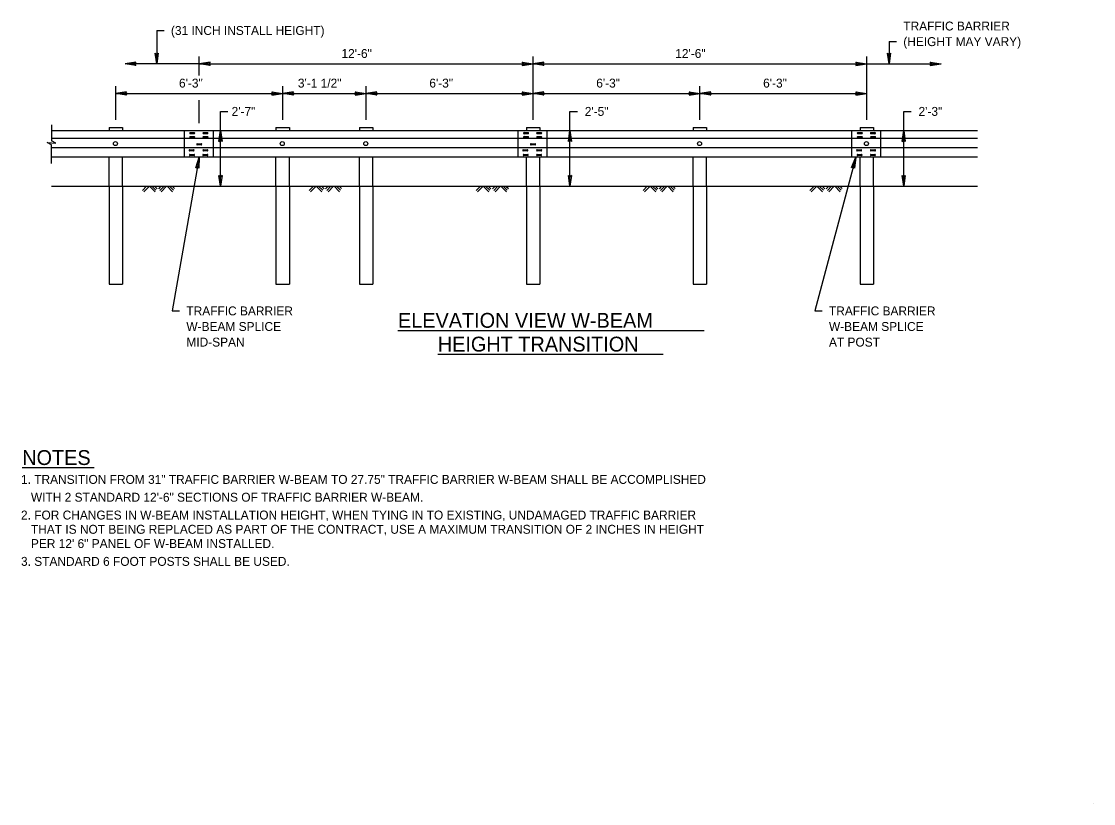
# Model space of a CAD drawing. Extents: x 12.39 to 19.62, y 5.98 to 15.84.
# Drawn here: x 12.4 to 19.62, y 5.98 to 11.25 of the extents above; entities that cross this region are included whole.
import ezdxf

# ---------------------------------------------------------------- set-up
doc = ezdxf.new("R2010")
doc.units = 0
for name, color, linetype in [('DETL-DIMS', 7, 'Continuous'), ('DETL-LINE', 7, 'Continuous'), ('DETL-NOTE', 7, 'Continuous'), ('DETL-PATT', 7, 'Continuous'), ('DETL-TITL', 7, 'Continuous'), ('TTLB-TEXT', 7, 'Continuous')]:
    doc.layers.add(name, color=color, linetype=linetype)

msp = doc.modelspace()

# ---------------------------------------------------------------- linework, layer by layer
at = {"layer": 'DETL-DIMS'}
for p, q in [((13.311, 11.1902), (13.311, 10.9652)), ((13.311, 11.1902), (13.361, 11.1902)), ((18.2435, 11.1152), (18.2435, 10.9652)), ((18.2435, 11.1152), (18.2935, 11.1152)), ((13.3004, 11.0381), (13.311, 10.9652)), ((13.3004, 11.0381), (13.311, 11.029)), ((13.3216, 11.0381), (13.311, 10.9652)), ((13.3216, 11.0381), (13.311, 11.029)), ((13.5972, 10.8864), (13.5972, 11.0152)), ((15.8453, 10.5879), (15.8453, 11.0152)), ((18.0935, 10.5879), (18.0935, 11.0152)), ((18.2329, 11.0381), (18.2435, 10.9652)), ((18.2329, 11.0381), (18.2435, 11.029)), ((18.2541, 11.0381), (18.2435, 10.9652)), ((18.2541, 11.0381), (18.2435, 11.029)), ((13.1701, 10.9758), (13.0972, 10.9652)), ((13.1701, 10.9546), (13.0972, 10.9652)), ((13.5972, 10.9652), (13.0972, 10.9652)), ((13.1701, 10.9758), (13.161, 10.9652)), ((13.1701, 10.9546), (13.161, 10.9652)), ((13.6701, 10.9758), (13.5972, 10.9652)), ((13.5972, 10.9652), (15.8453, 10.9652)), ((13.6701, 10.9546), (13.5972, 10.9652)), ((13.6701, 10.9758), (13.661, 10.9652)), ((13.6701, 10.9546), (13.661, 10.9652)), ((15.7724, 10.9758), (15.8453, 10.9652)), ((15.7724, 10.9758), (15.7815, 10.9652)), ((15.7724, 10.9546), (15.8453, 10.9652)), ((15.7724, 10.9546), (15.7815, 10.9652)), ((15.9182, 10.9758), (15.8453, 10.9652)), ((15.8453, 10.9652), (18.0935, 10.9652)), ((15.9182, 10.9546), (15.8453, 10.9652)), ((15.9182, 10.9758), (15.9091, 10.9652)), ((15.9182, 10.9546), (15.9091, 10.9652)), ((18.0206, 10.9758), (18.0935, 10.9652)), ((18.0206, 10.9758), (18.0297, 10.9652)), ((18.0206, 10.9546), (18.0935, 10.9652)), ((18.0206, 10.9546), (18.0297, 10.9652)), ((18.0935, 10.9652), (18.5935, 10.9652)), ((18.5206, 10.9758), (18.5935, 10.9652)), ((18.5206, 10.9758), (18.5297, 10.9652)), ((18.5206, 10.9546), (18.5935, 10.9652)), ((18.5206, 10.9546), (18.5297, 10.9652)), ((13.0351, 10.5879), (13.0351, 10.8159)), ((13.108, 10.7765), (13.0351, 10.7659)), ((13.0351, 10.7659), (14.1592, 10.7659)), ((13.108, 10.7553), (13.0351, 10.7659)), ((13.108, 10.7765), (13.0989, 10.7659)), ((13.108, 10.7553), (13.0989, 10.7659)), ((14.0863, 10.7765), (14.1592, 10.7659)), ((14.0863, 10.7765), (14.0954, 10.7659)), ((14.0863, 10.7553), (14.1592, 10.7659)), ((14.0863, 10.7553), (14.0954, 10.7659)), ((14.1592, 10.5879), (14.1592, 10.8159)), ((14.2321, 10.7765), (14.1592, 10.7659)), ((14.1592, 10.7659), (14.7212, 10.7659)), ((14.2321, 10.7553), (14.1592, 10.7659)), ((14.2321, 10.7765), (14.223, 10.7659)), ((14.2321, 10.7553), (14.223, 10.7659)), ((14.6483, 10.7765), (14.7212, 10.7659)), ((14.6483, 10.7765), (14.6574, 10.7659)), ((14.6483, 10.7553), (14.7212, 10.7659)), ((14.6483, 10.7553), (14.6574, 10.7659)), ((14.7212, 10.5879), (14.7212, 10.8159)), ((14.7941, 10.7765), (14.7212, 10.7659)), ((14.7212, 10.7659), (15.8453, 10.7659)), ((14.7941, 10.7553), (14.7212, 10.7659)), ((14.7941, 10.7765), (14.785, 10.7659)), ((14.7941, 10.7553), (14.785, 10.7659)), ((15.7724, 10.7765), (15.8453, 10.7659)), ((15.7724, 10.7765), (15.7815, 10.7659)), ((15.7724, 10.7553), (15.8453, 10.7659)), ((15.7724, 10.7553), (15.7815, 10.7659)), ((15.9182, 10.7765), (15.8453, 10.7659)), ((15.8453, 10.7659), (16.9694, 10.7659)), ((15.9182, 10.7553), (15.8453, 10.7659)), ((15.9182, 10.7765), (15.9091, 10.7659)), ((15.9182, 10.7553), (15.9091, 10.7659)), ((16.8965, 10.7765), (16.9694, 10.7659)), ((16.8965, 10.7765), (16.9056, 10.7659)), ((16.8965, 10.7553), (16.9694, 10.7659)), ((16.8965, 10.7553), (16.9056, 10.7659)), ((16.9694, 10.5879), (16.9694, 10.8159)), ((17.0423, 10.7765), (16.9694, 10.7659)), ((16.9694, 10.7659), (18.0935, 10.7659)), ((17.0423, 10.7553), (16.9694, 10.7659)), ((17.0423, 10.7765), (17.0332, 10.7659)), ((17.0423, 10.7553), (17.0332, 10.7659)), ((18.0206, 10.7765), (18.0935, 10.7659)), ((18.0206, 10.7765), (18.0297, 10.7659)), ((18.0206, 10.7553), (18.0935, 10.7659)), ((18.0206, 10.7553), (18.0297, 10.7659)), ((13.5972, 10.5659), (13.5972, 10.7216)), ((13.7403, 10.5159), (13.7403, 10.6454)), ((13.7403, 10.6454), (13.7903, 10.6454)), ((16.0939, 10.5159), (16.0939, 10.6454)), ((16.0939, 10.6454), (16.1439, 10.6454)), ((18.3421, 10.5159), (18.3421, 10.6454)), ((18.3421, 10.6454), (18.3921, 10.6454)), ((13.7297, 10.443), (13.7403, 10.5159)), ((13.7403, 10.1413), (13.7403, 10.5159)), ((13.7509, 10.443), (13.7403, 10.5159)), ((16.0833, 10.443), (16.0939, 10.5159)), ((16.0939, 10.1413), (16.0939, 10.5159)), ((16.1045, 10.443), (16.0939, 10.5159)), ((18.3315, 10.443), (18.3421, 10.5159)), ((18.3421, 10.1413), (18.3421, 10.5159)), ((18.3527, 10.443), (18.3421, 10.5159)), ((13.7297, 10.443), (13.7403, 10.4521)), ((13.7509, 10.443), (13.7403, 10.4521)), ((16.0833, 10.443), (16.0939, 10.4521)), ((16.1045, 10.443), (16.0939, 10.4521)), ((18.3315, 10.443), (18.3421, 10.4521)), ((18.3527, 10.443), (18.3421, 10.4521)), ((13.5972, 10.3361), (13.4148, 9.3018)), ((13.5741, 10.2661), (13.5972, 10.3361)), ((13.5949, 10.2625), (13.5972, 10.3361)), ((18.02, 10.3361), (17.7429, 9.3018)), ((17.9909, 10.2684), (18.02, 10.3361)), ((18.0114, 10.2629), (18.02, 10.3361)), ((13.5741, 10.2661), (13.5861, 10.2733)), ((13.5949, 10.2625), (13.5861, 10.2733)), ((17.9909, 10.2684), (18.0035, 10.2745)), ((18.0114, 10.2629), (18.0035, 10.2745)), ((13.7297, 10.2142), (13.7403, 10.1413)), ((13.7297, 10.2142), (13.7403, 10.2051)), ((13.7509, 10.2142), (13.7403, 10.1413)), ((13.7509, 10.2142), (13.7403, 10.2051)), ((16.0833, 10.2142), (16.0939, 10.1413)), ((16.0833, 10.2142), (16.0939, 10.2051)), ((16.1045, 10.2142), (16.0939, 10.1413)), ((16.1045, 10.2142), (16.0939, 10.2051)), ((18.3315, 10.2142), (18.3421, 10.1413)), ((18.3315, 10.2142), (18.3421, 10.2051)), ((18.3527, 10.2142), (18.3421, 10.1413)), ((18.3527, 10.2142), (18.3421, 10.2051)), ((13.4148, 9.3018), (13.4648, 9.3018)), ((17.7429, 9.3018), (17.7929, 9.3018))]:
    msp.add_line(p, q, dxfattribs=at)
for points in [[(13.3216, 11.0381), (13.311, 10.9652), (13.3004, 11.0381), (13.311, 11.029)], [(18.2541, 11.0381), (18.2435, 10.9652), (18.2329, 11.0381), (18.2435, 11.029)], [(13.1701, 10.9546), (13.0972, 10.9652), (13.1701, 10.9758), (13.161, 10.9652)], [(13.6701, 10.9546), (13.5972, 10.9652), (13.6701, 10.9758), (13.661, 10.9652)], [(15.7724, 10.9758), (15.8453, 10.9652), (15.7724, 10.9546), (15.7815, 10.9652)], [(15.9182, 10.9546), (15.8453, 10.9652), (15.9182, 10.9758), (15.9091, 10.9652)], [(18.0206, 10.9758), (18.0935, 10.9652), (18.0206, 10.9546), (18.0297, 10.9652)], [(18.5206, 10.9758), (18.5935, 10.9652), (18.5206, 10.9546), (18.5297, 10.9652)], [(13.108, 10.7553), (13.0351, 10.7659), (13.108, 10.7765), (13.0989, 10.7659)], [(14.0863, 10.7765), (14.1592, 10.7659), (14.0863, 10.7553), (14.0954, 10.7659)], [(14.2321, 10.7553), (14.1592, 10.7659), (14.2321, 10.7765), (14.223, 10.7659)], [(14.6483, 10.7765), (14.7212, 10.7659), (14.6483, 10.7553), (14.6574, 10.7659)], [(14.7941, 10.7553), (14.7212, 10.7659), (14.7941, 10.7765), (14.785, 10.7659)], [(15.7724, 10.7765), (15.8453, 10.7659), (15.7724, 10.7553), (15.7815, 10.7659)], [(15.9182, 10.7553), (15.8453, 10.7659), (15.9182, 10.7765), (15.9091, 10.7659)], [(16.8965, 10.7765), (16.9694, 10.7659), (16.8965, 10.7553), (16.9056, 10.7659)], [(17.0423, 10.7553), (16.9694, 10.7659), (17.0423, 10.7765), (17.0332, 10.7659)], [(18.0206, 10.7765), (18.0935, 10.7659), (18.0206, 10.7553), (18.0297, 10.7659)], [(13.7297, 10.443), (13.7403, 10.5159), (13.7509, 10.443), (13.7403, 10.4521)], [(16.0833, 10.443), (16.0939, 10.5159), (16.1045, 10.443), (16.0939, 10.4521)], [(18.3315, 10.443), (18.3421, 10.5159), (18.3527, 10.443), (18.3421, 10.4521)], [(13.5741, 10.2661), (13.5972, 10.3361), (13.5949, 10.2625), (13.5861, 10.2733)], [(17.9909, 10.2684), (18.02, 10.3361), (18.0114, 10.2629), (18.0035, 10.2745)], [(13.7509, 10.2142), (13.7403, 10.1413), (13.7297, 10.2142), (13.7403, 10.2051)], [(16.1045, 10.2142), (16.0939, 10.1413), (16.0833, 10.2142), (16.0939, 10.2051)], [(18.3527, 10.2142), (18.3421, 10.1413), (18.3315, 10.2142), (18.3421, 10.2051)]]:
    msp.add_lwpolyline(points, close=True, dxfattribs=at)
at = {"layer": 'DETL-LINE'}
for p, q in [((12.6022, 10.5543), (12.6022, 10.4476)), ((12.6022, 10.5159), (13.8777, 10.5159)), ((12.9901, 10.5379), (12.9901, 10.5159)), ((12.9901, 10.5379), (13.0801, 10.5379)), ((13.0801, 10.5379), (13.0801, 10.5159)), ((13.4952, 10.5152), (13.4952, 10.3361)), ((13.5367, 10.5034), (13.5637, 10.5034)), ((13.5637, 10.4954), (13.5367, 10.4954)), ((13.5367, 10.4762), (13.5637, 10.4762)), ((13.6252, 10.5034), (13.6523, 10.5034)), ((13.6523, 10.4954), (13.6252, 10.4954)), ((13.6259, 10.4756), (13.6528, 10.4756)), ((13.6903, 10.5152), (13.6903, 10.3361)), ((13.8777, 10.5159), (16.1259, 10.5159)), ((14.1142, 10.5379), (14.1142, 10.5159)), ((14.1142, 10.5379), (14.2042, 10.5379)), ((14.2042, 10.5379), (14.2042, 10.5159)), ((14.6763, 10.5379), (14.6763, 10.5159)), ((14.6763, 10.5379), (14.7662, 10.5379)), ((14.7662, 10.5379), (14.7662, 10.5159)), ((15.7433, 10.5152), (15.7433, 10.3361)), ((15.7849, 10.5034), (15.8118, 10.5034)), ((15.8118, 10.4954), (15.7849, 10.4954)), ((15.7849, 10.4762), (15.8118, 10.4762)), ((15.8004, 10.5379), (15.8004, 10.5159)), ((15.8004, 10.5379), (15.8903, 10.5379)), ((15.8734, 10.5034), (15.9005, 10.5034)), ((15.9005, 10.4954), (15.8734, 10.4954)), ((15.8741, 10.4756), (15.9009, 10.4756)), ((15.8903, 10.5379), (15.8903, 10.5159)), ((15.9384, 10.5152), (15.9384, 10.3361)), ((16.1259, 10.5159), (18.3741, 10.5159)), ((16.9244, 10.5379), (16.9244, 10.5159)), ((16.9244, 10.5379), (17.0144, 10.5379)), ((17.0144, 10.5379), (17.0144, 10.5159)), ((17.9915, 10.5152), (17.9915, 10.3361)), ((18.033, 10.5034), (18.06, 10.5034)), ((18.06, 10.4954), (18.033, 10.4954)), ((18.033, 10.4762), (18.06, 10.4762)), ((18.0485, 10.5379), (18.1385, 10.5379)), ((18.0485, 10.5379), (18.0485, 10.5159)), ((18.1216, 10.5034), (18.1487, 10.5034)), ((18.1487, 10.4954), (18.1216, 10.4954)), ((18.1222, 10.4756), (18.1491, 10.4756)), ((18.1385, 10.5379), (18.1385, 10.5159)), ((18.1866, 10.5152), (18.1866, 10.3361)), ((18.3741, 10.5159), (18.8393, 10.5159)), ((12.6022, 10.4191), (12.572, 10.4355)), ((12.572, 10.4355), (12.631, 10.4308)), ((18.8393, 10.4635), (12.6022, 10.4635)), ((12.631, 10.4308), (12.6022, 10.4476)), ((12.6022, 10.294), (12.6022, 10.4191)), ((18.8393, 10.3992), (12.6022, 10.3992)), ((13.5637, 10.4682), (13.5367, 10.4682)), ((13.5837, 10.4277), (13.6106, 10.4277)), ((13.6106, 10.4197), (13.5837, 10.4197)), ((13.6528, 10.4676), (13.6259, 10.4676)), ((15.8118, 10.4682), (15.7849, 10.4682)), ((15.8318, 10.4277), (15.8588, 10.4277)), ((15.8588, 10.4197), (15.8318, 10.4197)), ((15.9009, 10.4676), (15.8741, 10.4676)), ((18.06, 10.4682), (18.033, 10.4682)), ((18.1491, 10.4676), (18.1222, 10.4676)), ((18.8393, 10.3361), (12.6022, 10.3361)), ((12.9901, 10.1413), (12.9901, 10.3361)), ((13.0801, 10.1413), (13.0801, 10.3361)), ((13.5318, 10.3873), (13.559, 10.3873)), ((13.559, 10.3793), (13.5318, 10.3793)), ((13.5349, 10.356), (13.5619, 10.356)), ((13.5619, 10.3481), (13.5349, 10.3481)), ((13.6245, 10.3557), (13.6516, 10.3557)), ((13.6516, 10.3476), (13.6245, 10.3476)), ((13.6252, 10.3874), (13.6521, 10.3874)), ((13.6521, 10.3794), (13.6252, 10.3794)), ((14.1142, 10.1413), (14.1142, 10.3361)), ((14.2042, 10.1413), (14.2042, 10.3361)), ((14.6763, 10.1413), (14.6763, 10.3361)), ((14.7662, 10.1413), (14.7662, 10.3361)), ((15.78, 10.3873), (15.8071, 10.3873)), ((15.8071, 10.3793), (15.78, 10.3793)), ((15.7831, 10.356), (15.8101, 10.356)), ((15.8101, 10.3481), (15.7831, 10.3481)), ((15.8004, 10.1413), (15.8004, 10.3361)), ((15.8727, 10.3557), (15.8998, 10.3557)), ((15.8998, 10.3476), (15.8727, 10.3476)), ((15.8734, 10.3874), (15.9003, 10.3874)), ((15.9003, 10.3794), (15.8734, 10.3794)), ((15.8903, 10.1413), (15.8903, 10.3361)), ((16.9244, 10.1413), (16.9244, 10.3361)), ((17.0144, 10.1413), (17.0144, 10.3361)), ((18.0282, 10.3873), (18.0553, 10.3873)), ((18.0553, 10.3793), (18.0282, 10.3793)), ((18.0312, 10.356), (18.0583, 10.356)), ((18.0583, 10.3481), (18.0312, 10.3481)), ((18.0485, 10.1413), (18.0485, 10.3361)), ((18.1209, 10.3557), (18.1479, 10.3557)), ((18.1479, 10.3476), (18.1209, 10.3476)), ((18.1216, 10.3874), (18.1484, 10.3874)), ((18.1484, 10.3794), (18.1216, 10.3794)), ((18.1385, 10.1413), (18.1385, 10.3361)), ((12.6022, 10.1413), (18.8393, 10.1413)), ((12.9901, 10.1413), (12.9901, 9.4818)), ((13.0801, 10.1413), (13.0801, 9.4818)), ((14.1142, 10.1413), (14.1142, 9.4818)), ((14.2042, 10.1413), (14.2042, 9.4818)), ((14.6763, 10.1413), (14.6763, 9.4818)), ((14.7662, 10.1413), (14.7662, 9.4818)), ((15.8004, 10.1413), (15.8004, 9.4818)), ((15.8903, 10.1413), (15.8903, 9.4818)), ((16.9244, 10.1413), (16.9244, 9.4818)), ((17.0144, 10.1413), (17.0144, 9.4818)), ((18.0485, 10.1413), (18.0485, 9.4818)), ((18.1385, 10.1413), (18.1385, 9.4818)), ((12.9901, 9.4818), (13.0802, 9.4818)), ((14.1142, 9.4818), (14.2042, 9.4818)), ((14.6763, 9.4818), (14.7663, 9.4818)), ((15.8004, 9.4818), (15.8904, 9.4818)), ((16.9244, 9.4818), (17.0145, 9.4818)), ((18.0485, 9.4818), (18.1385, 9.4818))]:
    msp.add_line(p, q, dxfattribs=at)
for centre in [(13.0327, 10.4286), (14.1568, 10.4286), (14.7188, 10.4286), (16.967, 10.4286), (18.0911, 10.4286)]:
    msp.add_circle(centre, 0.0135, dxfattribs=at)
for centre, start, end in [((13.5371, 10.4994), 96.52857, 263.47143), ((13.5371, 10.4722), 96.52857, 263.47143), ((13.5632, 10.4994), 276.52857, 83.47143), ((13.5632, 10.4722), 276.52857, 83.47143), ((13.6257, 10.4994), 96.52857, 263.47143), ((13.6262, 10.4716), 96.52857, 263.47143), ((13.6518, 10.4994), 276.52857, 83.47143), ((13.6523, 10.4716), 276.52857, 83.47143), ((15.7853, 10.4722), 96.52857, 263.47143), ((15.7853, 10.4994), 96.52857, 263.47143), ((15.8114, 10.4722), 276.52857, 83.47143), ((15.8114, 10.4994), 276.52857, 83.47143), ((15.8739, 10.4994), 96.52857, 263.47143), ((15.8744, 10.4716), 96.52857, 263.47143), ((15.9, 10.4994), 276.52857, 83.47143), ((15.9005, 10.4716), 276.52857, 83.47143), ((18.0335, 10.4994), 96.52857, 263.47143), ((18.0335, 10.4722), 96.52857, 263.47143), ((18.0596, 10.4994), 276.52857, 83.47143), ((18.0596, 10.4722), 276.52857, 83.47143), ((18.122, 10.4994), 96.52857, 263.47143), ((18.1226, 10.4716), 96.52857, 263.47143), ((18.1481, 10.4994), 276.52857, 83.47143), ((18.1487, 10.4716), 276.52857, 83.47143), ((13.5841, 10.4237), 96.52857, 263.47143), ((13.6102, 10.4237), 276.52857, 83.47143), ((15.8323, 10.4237), 96.52857, 263.47143), ((15.8584, 10.4237), 276.52857, 83.47143), ((13.5324, 10.3833), 96.52857, 263.47143), ((13.5354, 10.352), 96.52857, 263.47143), ((13.5585, 10.3833), 276.52857, 83.47143), ((13.5615, 10.352), 276.52857, 83.47143), ((13.6251, 10.3517), 96.52857, 263.47143), ((13.6256, 10.3834), 96.52857, 263.47143), ((13.6512, 10.3517), 276.52857, 83.47143), ((13.6517, 10.3834), 276.52857, 83.47143), ((15.7805, 10.3833), 96.52857, 263.47143), ((15.7835, 10.352), 96.52857, 263.47143), ((15.8066, 10.3833), 276.52857, 83.47143), ((15.8096, 10.352), 276.52857, 83.47143), ((15.8732, 10.3517), 96.52857, 263.47143), ((15.8738, 10.3834), 96.52857, 263.47143), ((15.8993, 10.3517), 276.52857, 83.47143), ((15.8999, 10.3834), 276.52857, 83.47143), ((18.0287, 10.3833), 96.52857, 263.47143), ((18.0317, 10.352), 96.52857, 263.47143), ((18.0548, 10.3833), 276.52857, 83.47143), ((18.0578, 10.352), 276.52857, 83.47143), ((18.1214, 10.3517), 96.52857, 263.47143), ((18.1219, 10.3834), 96.52857, 263.47143), ((18.1475, 10.3517), 276.52857, 83.47143), ((18.148, 10.3834), 276.52857, 83.47143)]:
    msp.add_arc(centre, 0.00406, start, end, dxfattribs=at)
at = {"layer": 'DETL-NOTE'}
msp.add_line((12.405, 8.2472), (12.8898, 8.2472), dxfattribs=at)
at = {"layer": 'DETL-PATT'}
for p, q in [((13.2423, 10.1413), (13.214, 10.1126)), ((13.2236, 10.1043), (13.259, 10.1403)), ((13.2637, 10.1404), (13.2998, 10.1048)), ((13.3059, 10.1146), (13.2794, 10.1404)), ((13.2978, 10.1406), (13.3136, 10.125)), ((13.324, 10.1228), (13.3418, 10.1408)), ((13.3599, 10.141), (13.3321, 10.1126)), ((13.3415, 10.1042), (13.3776, 10.141)), ((13.3809, 10.1411), (13.4179, 10.1048)), ((13.4238, 10.1146), (13.3967, 10.1411)), ((13.4149, 10.1413), (13.4316, 10.1251)), ((14.3664, 10.1413), (14.3381, 10.1126)), ((14.3477, 10.1043), (14.3831, 10.1403)), ((14.3878, 10.1404), (14.4239, 10.1048)), ((14.43, 10.1146), (14.4035, 10.1404)), ((14.4218, 10.1406), (14.4377, 10.125)), ((14.4481, 10.1228), (14.4659, 10.1408)), ((14.484, 10.141), (14.4562, 10.1126)), ((14.4656, 10.1042), (14.5017, 10.141)), ((14.505, 10.1411), (14.542, 10.1048)), ((14.5479, 10.1146), (14.5208, 10.1411)), ((14.539, 10.1413), (14.5557, 10.1251)), ((15.4905, 10.1413), (15.4622, 10.1126)), ((15.4718, 10.1043), (15.5071, 10.1403)), ((15.5118, 10.1404), (15.548, 10.1048)), ((15.5541, 10.1146), (15.5276, 10.1404)), ((15.5459, 10.1406), (15.5617, 10.125)), ((15.5721, 10.1228), (15.5899, 10.1408)), ((15.6081, 10.141), (15.5803, 10.1126)), ((15.5897, 10.1042), (15.6257, 10.141)), ((15.6291, 10.1411), (15.6661, 10.1048)), ((15.672, 10.1146), (15.6449, 10.1411)), ((15.6631, 10.1413), (15.6797, 10.1251)), ((16.6146, 10.1413), (16.5863, 10.1126)), ((16.5959, 10.1043), (16.6312, 10.1403)), ((16.6359, 10.1404), (16.6721, 10.1048)), ((16.6782, 10.1146), (16.6517, 10.1404)), ((16.67, 10.1406), (16.6858, 10.125)), ((16.6962, 10.1228), (16.714, 10.1408)), ((16.7322, 10.141), (16.7043, 10.1126)), ((16.7138, 10.1042), (16.7498, 10.141)), ((16.7532, 10.1411), (16.7902, 10.1048)), ((16.7961, 10.1146), (16.769, 10.1411)), ((16.7872, 10.1413), (16.8038, 10.1251)), ((17.7387, 10.1413), (17.7104, 10.1126)), ((17.7199, 10.1043), (17.7553, 10.1403)), ((17.76, 10.1404), (17.7962, 10.1048)), ((17.8023, 10.1146), (17.7758, 10.1404)), ((17.7941, 10.1406), (17.8099, 10.125)), ((17.8203, 10.1228), (17.8381, 10.1408)), ((17.8563, 10.141), (17.8284, 10.1126)), ((17.8379, 10.1042), (17.8739, 10.141)), ((17.8773, 10.1411), (17.9142, 10.1048)), ((17.9202, 10.1146), (17.893, 10.1411)), ((17.9113, 10.1413), (17.9279, 10.1251))]:
    msp.add_line(p, q, dxfattribs=at)
at = {"layer": 'DETL-TITL'}
for p, q in [((14.9359, 9.17), (16.9989, 9.17)), ((15.2039, 9.01), (16.7227, 9.01))]:
    msp.add_line(p, q, dxfattribs=at)
at = {"layer": 'TTLB-TEXT'}
msp.add_line((19.6208, 5.9844), (19.6208, 5.9844), dxfattribs=at)

# ---------------------------------------------------------------- texts
at = {"layer": 'DETL-NOTE'}
for s, height, p in [('(31 INCH INSTALL HEIGHT)', 0.06, (13.4067, 11.1602)), ('TRAFFIC BARRIER', 0.06, (18.3393, 11.1902)), ('(HEIGHT MAY VARY)', 0.06, (18.3393, 11.0852)), ('12\'-6"', 0.06, (14.5551, 11.0052)), ('12\'-6"', 0.06, (16.8033, 11.0052)), ('6\'-3"', 0.06, (13.461, 10.8059)), ('3\'-1 1/2"', 0.06, (14.2616, 10.8059)), ('6\'-3"', 0.06, (15.1471, 10.8059)), ('6\'-3"', 0.06, (16.2712, 10.8059)), ('6\'-3"', 0.06, (17.3953, 10.8059)), ('2\'-7"', 0.06, (13.8153, 10.6154)), ('2\'-5"', 0.06, (16.1939, 10.6154)), ('2\'-3"', 0.06, (18.4421, 10.6154)), ('TRAFFIC BARRIER', 0.06, (13.5106, 9.2718)), ('TRAFFIC BARRIER', 0.06, (17.8387, 9.2718)), ('W-BEAM SPLICE', 0.06, (13.5106, 9.1668)), ('W-BEAM SPLICE', 0.06, (17.8387, 9.1668)), ('MID-SPAN', 0.06, (13.5106, 9.0618)), ('AT POST', 0.06, (17.8387, 9.0618)), ('NOTES', 0.1, (12.405, 8.2643)), ('2. FOR CHANGES IN W-BEAM INSTALLATION HEIGHT, WHEN TYING IN TO EXISTING, UNDAMAGED TRAFFIC BARRIER', 0.06, (12.3966, 7.8972)), ('   THAT IS NOT BEING REPLACED AS PART OF THE CONTRACT, USE A MAXIMUM TRANSITION OF 2 INCHES IN HEIGHT', 0.06, (12.3966, 7.8012)), ('   PER 12\' 6" PANEL OF W-BEAM INSTALLED.', 0.06, (12.3966, 7.7052)), ('3. STANDARD 6 FOOT POSTS SHALL BE USED.', 0.06, (12.3966, 7.5852))]:
    msp.add_text(s, height=height, rotation=360, dxfattribs=at).set_placement(p)
for s, p in [('1. TRANSITION FROM 31" TRAFFIC BARRIER W-BEAM TO 27.75" TRAFFIC BARRIER W-BEAM SHALL BE ACCOMPLISHED', (12.3966, 8.1372)), ('   WITH 2 STANDARD 12\'-6" SECTIONS OF TRAFFIC BARRIER W-BEAM.', (12.3966, 8.0172))]:
    msp.add_text(s, height=0.06, dxfattribs=at).set_placement(p)
at = {"layer": 'DETL-TITL'}
for s, p in [('ELEVATION VIEW W-BEAM', (14.9359, 9.1883)), ('HEIGHT TRANSITION', (15.2039, 9.0283))]:
    msp.add_text(s, height=0.1, rotation=360, dxfattribs=at).set_placement(p)

doc.saveas('drawing.dxf')
